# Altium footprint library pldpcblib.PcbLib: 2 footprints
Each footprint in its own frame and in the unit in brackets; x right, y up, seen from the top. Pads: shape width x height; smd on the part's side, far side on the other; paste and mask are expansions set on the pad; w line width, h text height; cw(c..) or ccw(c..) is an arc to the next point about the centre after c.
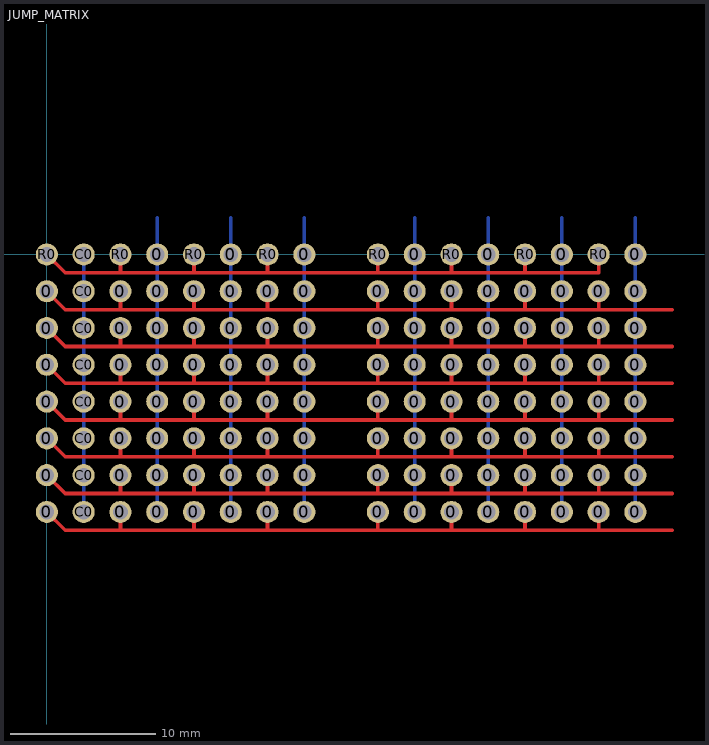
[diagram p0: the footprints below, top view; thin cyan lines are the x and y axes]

## JUMP_MATRIX [mil]
pads (128):
  round 60 hole 40: 0(0,-700) 0(0,-600) 0(0,-500) 0(0,-400) 0(0,-300) 0(0,-200) 0(0,-100) 0(200,-700) 0(200,-600) 0(200,-500) 0(200,-400) 0(200,-300) 0(200,-200) 0(200,-100) 0(300,-700) 0(300,-600) 0(300,-500) 0(300,-400) 0(300,-300) 0(300,-200) 0(300,-100) 0(300,0) 0(400,-700) 0(400,-600) 0(400,-500) 0(400,-400) 0(400,-300) 0(400,-200) 0(400,-100) 0(500,-700) 0(500,-600) 0(500,-500) 0(500,-400) 0(500,-300) 0(500,-200) 0(500,-100) 0(500,0) 0(600,-700) 0(600,-600) 0(600,-500) 0(600,-400) 0(600,-300) 0(600,-200) 0(600,-100) 0(700,-700) 0(700,-600) 0(700,-500) 0(700,-400) 0(700,-300) 0(700,-200) 0(700,-100) 0(700,0) 0(900,-700) 0(900,-600) 0(900,-500) 0(900,-400) 0(900,-300) 0(900,-200) 0(900,-100) 0(1000,-700) 0(1000,-600) 0(1000,-500) 0(1000,-400) 0(1000,-300) 0(1000,-200) 0(1000,-100) 0(1000,0) 0(1100,-700) 0(1100,-600) 0(1100,-500) 0(1100,-400) 0(1100,-300) 0(1100,-200) 0(1100,-100) 0(1200,-700) 0(1200,-600) 0(1200,-500) 0(1200,-400) 0(1200,-300) 0(1200,-200) 0(1200,-100) 0(1200,0) 0(1300,-700) 0(1300,-600) 0(1300,-500) 0(1300,-400) 0(1300,-300) 0(1300,-200) 0(1300,-100) 0(1400,-700) 0(1400,-600) 0(1400,-500) 0(1400,-400) 0(1400,-300) 0(1400,-200) 0(1400,-100) 0(1400,0) 0(1500,-700) 0(1500,-600) 0(1500,-500) 0(1500,-400) 0(1500,-300) 0(1500,-200) 0(1500,-100) 0(1600,-700) 0(1600,-600) 0(1600,-500) 0(1600,-400) 0(1600,-300) 0(1600,-200) 0(1600,-100) 0(1600,0) C0(100,-700) C0(100,-600) C0(100,-500) C0(100,-400) C0(100,-300) C0(100,-200) C0(100,-100) C0(100,0) R0(0,0) R0(200,0) R0(400,0) R0(600,0) R0(900,0) R0(1100,0) R0(1300,0) R0(1500,0)
Top Layer:
  lines w10: 0,-700 50,-750 1700,-750 ; 0,-600 50,-650 1700,-650 ; 0,-500 50,-550 1700,-550 ; 0,-400 50,-450 1700,-450 ; 0,-300 50,-350 1700,-350 ; 0,-200 50,-250 1700,-250 ; 0,-100 50,-150 1700,-150 ; 0,0 50,-50 1500,-50 1500,0 ; 200,-750 200,-700 ; 200,-650 200,-600 ; 200,-550 200,-500 ; 200,-450 200,-400 ; 200,-350 200,-300 ; 200,-250 200,-200 ; 200,-150 200,-100 ; 200,-50 200,0 ; 400,-750 400,-700 ; 400,-650 400,-600 ; 400,-550 400,-500 ; 400,-450 400,-400 ; 400,-350 400,-300 ; 400,-250 400,-200 ; 400,-150 400,-100 ; 400,-50 400,0 ; 600,-750 600,-700 ; 600,-650 600,-600 ; 600,-550 600,-500 ; 600,-450 600,-400 ; 600,-350 600,-300 ; 600,-250 600,-200 ; 600,-150 600,-100 ; 600,-50 600,0 ; 900,-750 900,-700 ; 900,-650 900,-600 ; 900,-550 900,-500 ; 900,-450 900,-400 ; 900,-350 900,-300 ; 900,-250 900,-200 ; 900,-150 900,-100 ; 900,-50 900,0 ; 1100,-750 1100,-700 ; 1100,-650 1100,-600 ; 1100,-550 1100,-500 ; 1100,-450 1100,-400 ; 1100,-350 1100,-300 ; 1100,-250 1100,-200 ; 1100,-150 1100,-100 ; 1100,-50 1100,0 ; 1300,-750 1300,-700 ; 1300,-650 1300,-600 ; 1300,-550 1300,-500 ; 1300,-450 1300,-400 ; 1300,-350 1300,-300 ; 1300,-250 1300,-200 ; 1300,-150 1300,-100 ; 1300,-50 1300,0 ; 1500,-750 1500,-700 ; 1500,-650 1500,-600 ; 1500,-550 1500,-500 ; 1500,-450 1500,-400 ; 1500,-350 1500,-300 ; 1500,-250 1500,-200 ; 1500,-150 1500,-100
Bottom Layer:
  lines w10: 100,-700 100,0 ; 300,-700 300,100 ; 500,-700 500,100 ; 700,-700 700,100 ; 1000,-700 1000,100 ; 1200,-700 1200,100 ; 1400,-700 1400,100 ; 1600,-700 1600,100

## PCBComponent_1 [mil]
